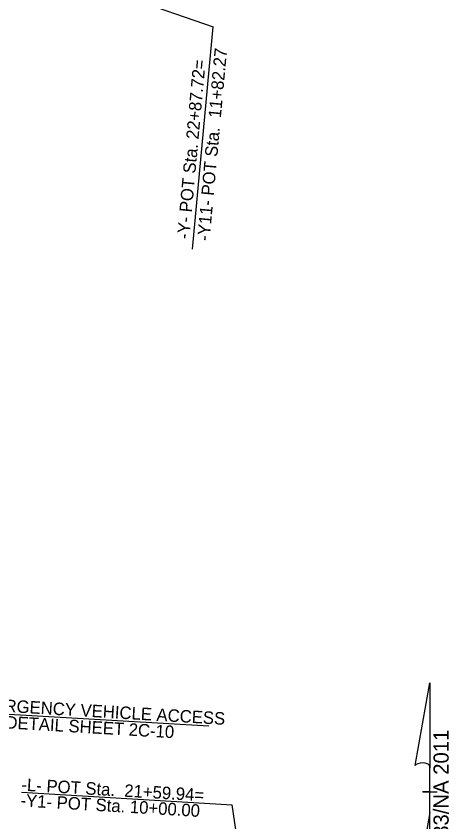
# Model space of a CAD drawing. Extents: x 2010838 to 2015151, y 441905 to 447792.
# Drawn here: x 2012241 to 2012483.5, y 445190.9 to 445642.5 of the extents above; entities that cross this region are included whole.
import ezdxf

# ---------------------------------------------------------------- set-up
doc = ezdxf.new("R2010")
doc.units = 0
for name, color, linetype in [('B - Border Text', 7, 'Continuous'), ('CLRD', 7, 'Continuous'), ('Default_10ft_LIDAR_Contou', 7, 'Continuous'), ('HATCH', 7, 'Continuous'), ('S-Existing Minor', 7, 'Continuous'), ('S-overhead electric', 7, 'Continuous'), ('TEXT-LG', 7, 'Continuous'), ('TEXT-MED', 7, 'Continuous')]:
    doc.layers.add(name, color=color, linetype=linetype)

msp = doc.modelspace()

# ---------------------------------------------------------------- linework, layer by layer
at = {"layer": 'B - Border Text'}
for p, q in [((2012464.59, 445222.49), (2012472.79, 445268.84)), ((2012472.84, 445268.84), (2012472.79, 445268.84)), ((2012472.84, 445268.84), (2012472.79, 445268.84)), ((2012472.84, 445268.84), (2012472.84, 445221.04)), ((2012472.84, 445196.24), (2012472.84, 445222.44)), ((2012472.84, 445221.04), (2012472.84, 445222.39)), ((2012468.84, 445207.84), (2012468.79, 445207.84)), ((2012472.39, 445207.84), (2012468.84, 445207.84)), ((2012468.89, 445207.84), (2012476.89, 445207.84)), ((2012472.84, 445196.24), (2012464.49, 445148.99)), ((2012472.89, 445149.19), (2012472.84, 445196.24))]:
    msp.add_line(p, q, dxfattribs=at)
msp.add_ellipse((2012468.73, 445221.99), major_axis=(4.23, -0.03), ratio=0.461098, start_param=0.216388, end_param=2.908219, dxfattribs=at)
at = {"layer": 'CLRD'}
msp.add_arc((2012603.65, 445449.83), 535, 123.0111, 176.5533, dxfattribs=at)
at = {"layer": 'Default_10ft_LIDAR_Contou'}
for p, q in [((2012136.9, 445711.31), (2012351.37, 445636.48)), ((2012339.92, 445512), (2012351.37, 445636.48)), ((2012244.04, 445207.49), (2012362.02, 445200.53)), ((2012397.34, 444964.38), (2012362.02, 445200.53))]:
    msp.add_line(p, q, dxfattribs=at)
at = {"layer": 'HATCH'}
for radius in [555.75, 514.25]:
    msp.add_arc((2012603.65, 445449.83), radius, 123.0111, 176.5533, dxfattribs=at)
at = {"layer": 'S-Existing Minor'}
msp.add_line((2012211.68, 445252.84), (2012349.06, 445244.74), dxfattribs=at)
at = {"layer": 'S-overhead electric'}
msp.add_arc((2012603.65, 445449.83), 500.25, 126.2999, 167.9015, dxfattribs=at)
at = {"layer": 'TEXT-LG'}
for radius, start, end in [(497.25, 125.5092, 168.553), (489.25, 124.1314, 169.5987)]:
    msp.add_arc((2012603.65, 445449.83), radius, start, end, dxfattribs=at)
at = {"layer": 'TEXT-MED'}
msp.add_arc((2012603.65, 445449.83), 498.25, 126.2999, 167.9015, dxfattribs=at)

# ---------------------------------------------------------------- texts
at = {"layer": 'B - Border Text'}
msp.add_text('NAD 83/NA 2011', height=8.5, rotation=90, dxfattribs=at).set_placement((2012483.36, 445155.41))
at = {"layer": 'Default_10ft_LIDAR_Contou'}
for s, rotation, p in [('-Y11- POT Sta.  11+82.27', 84.7467, (2012349.36, 445516.29)), ('-Y- POT Sta. 22+87.72=', 84.7467, (2012338.04, 445517.33)), ('-L- POT Sta.  21+59.94=', 356.6264, (2012243.82, 445208.45)), ('-Y1- POT Sta. 10+00.00', 356.6264, (2012243.3, 445199.59))]:
    msp.add_text(s, height=7, rotation=rotation, dxfattribs=at).set_placement(p)
at = {"layer": 'S-Existing Minor'}
for s, p in [('EMERGENCY VEHICLE ACCESS', (2012214.1, 445253.78)), ('SEE DETAIL SHEET 2C-10', (2012213.56, 445244.62))]:
    msp.add_text(s, height=7, rotation=356.6264, dxfattribs=at).set_placement(p)

doc.saveas('drawing.dxf')
